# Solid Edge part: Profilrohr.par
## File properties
Username: ahadarics
Dokumentum tartalom típus: 0
Author: ahadarics
Last saved by: ahadarics
Revision: 83
Sűrűség: 0,000 kg/m^3
Pontosság: 0,990
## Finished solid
Body 1: solid body, 6 faces, 6 edges, 0 vertices.
  Faces by surface: cone 2, cylinder 2, plane 2
  Edges by curve: circle 6
Bounding box of the edges (mm): 26.500 x 26.500 x 233.000, from (-13.25, -13.25, -211.5) to (13.25, 13.25, 21.5).
Cylindrical faces by radius (mm): R12.5 x1, R13.25 x1
Conical faces (half-angle, radius in mm at the cone's reference point): 15 deg R12.567 x2
Planar faces by outward normal: +z 1, -z 1
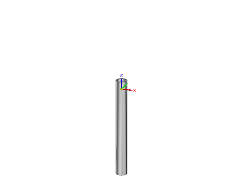
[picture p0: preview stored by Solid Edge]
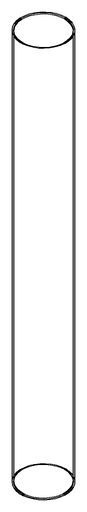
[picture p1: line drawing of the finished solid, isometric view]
